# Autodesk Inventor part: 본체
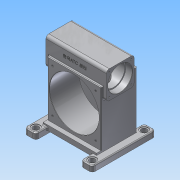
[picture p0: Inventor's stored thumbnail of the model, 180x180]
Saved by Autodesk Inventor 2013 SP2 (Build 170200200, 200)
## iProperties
Created: 2025-06
Part Number: 본체
Material: 알루미늄 6061
Document SubType Name: Sheet Metal
Designer: a
Density: 2.71 g/cm^3
Sheet Metal Rule: Default_mm
Mass: 7990.77 g
Surface Area: 3469.37 cm^2
Volume: 2948.62 cm^3
Author: a
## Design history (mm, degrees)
sketch "스케치3"
  geometry: L1 (-38, -48)-(38, -48); L2 (48, -38)-(48, 38); L3 (38, 48)-(-38, 48); L4 (-48, 38)-(-48, -38); L5 (-48, -48)-(48, 48); L6 (48, -48)-(-48, 48); L7 (-7, 48)-(-7, 55); L8 (-7, 55)-(-213, 55); L9 (-213, -70)-(-7, -70); L10 (-7, -70)-(-7, -48); L11 (-213, -70)-(-213, 55); A1 r 10 centre (38, 38) between (48, 38) and (38, 48); A2 r 10 centre (38, -38) between (38, -48) and (48, -38); A3 r 10 centre (-38, -38) between (-48, -38) and (-38, -48); A4 r 10 centre (-38, 38) between (-38, 48) and (-48, 38); 1 further point
  constraints: 22 end point, 10 point on line, 8 point on circle, 8 tangent, 4 centre point, 4 parallel, 4 perpendicular, 3 equal radius, 2 midpoint, 1 horizontal
  dimensions: "d0" = 96 distance of L6.start L5.end; "d3" = 96 distance of L5.end L6.end; "d4" = 206 distance of L9.start L9.end; "d6" = 7 distance of L7.start L7.end; "d7" = 22 distance of L9.end L10.end; "d8" = 261 distance between parallel lines of L11 L2; "d9" = 206 distance between parallel lines of L11 L7; "d21" = 10 radius of A1
extrude "돌출1" new body sketch "스케치3" stored distance "d10" = 210; taper "d11" = 0 deg
extrude "돌출2" join sketch "스케치3" stored distance "d12" = 186; taper "d13" = 0 deg
sketch "스케치4"
  geometry: L1 (0, 0)-(0, 125) reference; L2 (0, 125)-(186, 125) reference; L3 (186, 125)-(186, 0) reference; L4 (186, 0)-(0, 0) reference; L5 (211, -40)-(171, -40); L6 (171, -40)-(171, 180); L7 (171, 180)-(211, 180); L8 (211, 180)-(211, -40); 2 further points
  constraints: 8 end point, 2 parallel, 1 horizontal, 1 horizontal alignment, 1 midpoint, 1 perpendicular
  dimensions: "d14" = 220 distance of L7.end L5.start; "d16" = 40 distance of L5.start L5.end; "d17" = 118 distance from line of point (93, 70) L8
extrude "돌출3" join sketch "스케치4" stored distance "d18" = 20; taper "d19" = 0 deg
fillet "모깎기1" dims "d20" = 10
sketch "스케치5"
  geometry: L1 (110, -203)-(110, -223) reference; L2 (110, -223)-(-110, -223) reference; L3 (-110, -223)-(-110, -203) reference; L4 (-110, -203)-(110, -203) reference; L5 (-38, 48)-(38, 48) reference; L6 (48, 38)-(48, -38) reference; L7 (38, -48)-(-38, -48) reference; L8 (-48, -38)-(-48, 38) reference; L9 (110, -203)-(110, -223) reference; L10 (110, -223)-(-110, -223) reference; L11 (-110, -223)-(-110, -203) reference; L12 (-110, -203)-(110, -203) reference; L13 (-38, 48)-(38, 48) reference; L14 (48, 38)-(48, -38) reference; L15 (38, -48)-(-38, -48) reference; L16 (-48, -38)-(-48, 38) reference; C1 r 38.5 at (0, 0); A1 r 10 centre (-38, 38) between (-38, 48) and (-48, 38) reference; A2 r 10 centre (38, 38) between (48, 38) and (38, 48) reference; A3 r 10 centre (38, -38) between (38, -48) and (48, -38) reference; A4 r 10 centre (-38, -38) between (-48, -38) and (-38, -48) reference; A5 r 10 centre (-38, 38) between (-38, 48) and (-48, 38) reference; A6 r 10 centre (38, 38) between (48, 38) and (38, 48) reference; A7 r 10 centre (38, -38) between (38, -48) and (48, -38) reference; A8 r 10 centre (-38, -38) between (-48, -38) and (-38, -48) reference; 1 further point
  constraints: 1 centre point, 1 coincident
  dimensions: "d22" = 77 diameter of C1
extrude "돌출4" cut sketch "스케치5" stored distance "d25" = 20; taper "d26" = 0 deg
sketch "스케치6"
  geometry: C1 r 38.5 at (0, 0) reference; C2 r 42.5 at (0, 0)
  constraints: 1 centre point, 1 coincident
  dimensions: "d27" = 85 diameter of C2
extrude "돌출5" cut sketch "스케치6" distance "d28" = 23; taper "d29" = 0 deg
sketch "스케치8"
  geometry: L1 (48, 38)-(48, -38) reference; L2 (38, -48)-(-7, -48) reference; L3 (-7, -48)-(-7, -70) reference; L4 (-7, -70)-(-213, -70) reference; L5 (-213, -70)-(-213, 55) reference; L6 (-213, 55)-(-7, 55) reference; L7 (-7, 55)-(-7, 48) reference; L8 (-7, 48)-(38, 48) reference; L9 (-14, 55)-(-14, -47); L10 (-14, -47)-(-69, -47); L11 (-69, -47)-(-69, -62); L12 (-100, 55)-(-100, -70); L13 (-14, 55)-(-100, 55); L14 (-76, -66)-(-100, -66); L15 (-70, -63)-(-73, -63); L16 (-73, -63)-(-73, -63); C1 r 38.5 at (0, 0) reference; A1 r 10 centre (38, 38) between (48, 38) and (38, 48) reference; A2 r 10 centre (38, -38) between (38, -48) and (48, -38) reference; A3 r 3 centre (-76, -63) between (-76, -66) and (-73, -63); A4 r 1 centre (-70, -62) between (-70, -63) and (-69, -62); 3 further points
  constraints: 16 end point, 8 point on line, 5 perpendicular, 4 point on circle, 4 tangent, 2 centre point, 2 parallel, 1 collinear
  dimensions: "d51" = 100 horizontal distance of point (0, 0) L12.start; "d52" = 172 diameter of L9 L12; "d53" = 102 distance of L9.start L9.end; "d56" = 62 diameter of L11 L12; "d57" = 54 diameter of L16 L12; "d58" = 3 distance of L15.end point (-73, -66); "d59" = 16 distance of L10.end point (-69, -63); "d60" = 3 radius of A3; "d61" = 1 radius of A4
revolve "회전1" sketch "스케치8" stored, may be unused: angle "d40" = 90 deg
sketch "스케치9"
  geometry: L1 (110, -203)-(110, -223) reference; L2 (110, -223)-(-110, -223) reference; L3 (-110, -223)-(-110, -203) reference; L4 (-110, -203)-(110, -203) reference; L5 (-38, 48)-(38, 48) reference; L6 (48, 38)-(48, -38) reference; L7 (38, -48)-(-38, -48) reference; L8 (-48, -38)-(-48, 38) reference; C1 r 42.5 at (0, 0) reference; A1 r 10 centre (-38, 38) between (-38, 48) and (-48, 38) reference; A2 r 10 centre (38, 38) between (48, 38) and (38, 48) reference; A3 r 10 centre (38, -38) between (38, -48) and (48, -38) reference; A4 r 10 centre (-38, -38) between (-48, -38) and (-38, -48) reference; 4 further points
  constraints: 4 coincident
hole "구멍1" sketch "스케치9" at (-38, 38), (38, 38), (38, -38), (-38, -38) diameter "d44" = 4.917; stored, may be unused: countersink angle "d48" = 90 deg, drill point angle "d50" = 118 deg; dims "d45" = 12, "d46" = 4, "d47" = 2, "d49" = 14
chamfer "모따기2" distance "d62" = 1; stored, may be unused: second distance "d63" = 2, angle "d64" = 45 deg
sketch "스케치10"
  geometry: C1 r 87 at (93, -93) reference; 5 further points
  dimensions: "d65" = 150 distance of point (168, -18) point (18, -18); "d67" = 150 distance of point (18, -168) point (18, -18); "d68" = 75 horizontal distance of C1.centre point (18, -18); "d70" = 75 horizontal distance of C1.centre point (18, -168); "d71" = 75 horizontal distance of C1.centre point (168, -168); "d72" = 75 horizontal distance of point (168, -168) C1.centre; "d73" = 75 horizontal distance of point (168, -18) C1.centre; "d74" = 75 horizontal distance of C1.centre point (18, -18)
hole "구멍2" sketch "스케치10" at (18, -18), (168, -18), (168, -168), (18, -168) diameter "d75" = 6.647; stored, may be unused: countersink angle "d79" = 90 deg, drill point angle "d81" = 118 deg; dims "d76" = 16, "d77" = 4, "d78" = 2, "d80" = 18
sketch "스케치11"
  geometry: L1 (15, -206)-(171, -206) reference; L2 (0, -196)-(0, 0) reference; L3 (0, -189)-(186, -189); L4 (186, -189)-(186, -206); L5 (186, -206)-(0, -206); L6 (0, -206)-(0, -189); 3 further points
  constraints: 8 end point, 2 midpoint, 2 parallel, 1 coincident, 1 horizontal, 1 perpendicular, 1 point on line
  dimensions: "d82" = 17 distance of L5.end L3.start; "d84" = 186 distance of L3.start L3.end
extrude "돌출6" join sketch "스케치11" distance "d85" = 15; taper "d86" = 0 deg
sketch "스케치12"
  geometry: L1 (-15, 40)-(5, 40) reference; L2 (15, 30)-(15, 0) reference; L3 (0, 0)-(15, 0) reference; L4 (0, -140)-(0, 0) reference; L5 (15, -140)-(0, -140) reference; L6 (15, -140)-(15, -170) reference; L7 (5, -180)-(-15, -180) reference; L8 (-25, -170)-(-25, 30) reference; L9 (15, 0)-(171, 0) reference; L10 (171, 0)-(171, 30) reference; L11 (181, 40)-(201, 40) reference; L12 (211, 30)-(211, -170) reference; L13 (201, -180)-(181, -180) reference; L14 (171, -170)-(171, -140) reference; L15 (186, -140)-(171, -140) reference; L16 (186, 0)-(186, -140) reference; L17 (171, 0)-(186, 0) reference; L18 (171, -140)-(15, -140) reference; A1 r 10 centre (-15, 30) between (-15, 40) and (-25, 30) reference; A2 r 10 centre (5, 30) between (15, 30) and (5, 40) reference; A3 r 10 centre (5, -170) between (5, -180) and (15, -170) reference; A4 r 10 centre (-15, -170) between (-25, -170) and (-15, -180) reference; A5 r 10 centre (181, 30) between (181, 40) and (171, 30) reference; A6 r 10 centre (201, 30) between (211, 30) and (201, 40) reference; A7 r 10 centre (201, -170) between (201, -180) and (211, -170) reference; A8 r 10 centre (181, -170) between (171, -170) and (181, -180) reference; 5 further points
  dimensions: "d87" = 196 distance of point (191, 20) point (-5, 20); "d89" = 180 distance of point (-5, -160) point (-5, 20); "d90" = 90 vertical distance of point (93, -70) point (-5, 20); "d91" = 90 vertical distance of point (93, -70) point (-5, -160); "d92" = 98 horizontal distance of point (93, -70) point (-5, 20); "d100" = 98 horizontal distance of point (93, -70) point (191, 20); "d101" = 98 horizontal distance of point (191, -160) point (93, -70); "d102" = 90 vertical distance of point (191, -160) point (93, -70)
hole "구멍3" sketch "스케치12" at (-5, 20), (191, 20), (191, -160), (-5, -160) diameter "d93" = 20; stored, may be unused: countersink angle "d97" = 90 deg, drill point angle "d99" = 118 deg; dims "d94" = 16, "d95" = 28, "d96" = 2, "d98" = 18
fillet "모깎기2" dims "d103" = 3
fillet "모깎기3" dims "d104" = 3
sketch "스케치13"
  geometry: L1 (58.602, -6.892)-(142.435, -6.892); L2 (142.435, -6.892)-(142.435, -32.728); L3 (142.435, -32.728)-(58.602, -32.728); L4 (58.602, -32.728)-(58.602, -6.892); 1 further point
  constraints: 2 other
feature "엠보싱1" sketch "스케치13" dims "d105" = 0.5, "d106" = 0, "MinimumRemnant" = 1 (= 2 x Thickness)
fillet "모깎기4" dims "d107" = 1
node "솔리드1"
mirror "대칭1"
mirror "대칭2"
mirror "대칭3"
node "절단 모서리 투영1"
node "절단 모서리 투영2"
node "절단 모서리 투영3"
node "절단 모서리 투영6"
node "절단 모서리 투영7"
node "절단 모서리 투영8"
other parameters: "Thickness" = 0.5, "BendRadius" = 0.5 (= Thickness), "BendReliefWidth" = 0.5 (= Thickness), "BendReliefDepth" = 0.25 (= 0.5 x Thickness), "CornerReliefSize" = 2 (= 4 x Thickness), "SeamGap" = 0.01, "TransitionRadius" = 0.5 (= BendRadius), "JacobiRadiusSize" = 0.5 (= BendRadius), "GapSize" = 0.5 (= Thickness)
